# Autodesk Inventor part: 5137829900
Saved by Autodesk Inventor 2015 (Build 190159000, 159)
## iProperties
Created: 2020-07
Part Number: 5137829900
Checked By: TraceParts S.A.
Material: Generic
Catalog Web Link: www.traceparts.com
Document SubType Name: Modeling
Designer: TraceParts
Density: 1 g/cm^3
Appearance: Default
Company: TraceParts S.A.
Author: TraceParts
REFERENCE: 5137829900
DESIGN: CVAB-4000/400 N ECOWATT 0,45KW (230V 50/60HZ) N8 - 5137829900
SUPPLIER: Soler & Palau
TraceParts.PartNumber: 10-20122018-119636
TraceParts.PartTitle: CVAB/T-N_ECO
TraceParts.InstanceId: 10-20122018-1196363SL2A2IWXGLQZ48PNF08XPN57
TraceParts.PartStatus: Published
TraceParts.PartVersion: 1.0.2
TRACEPARTS: TRACEPARTS
TraceParts.PartLanguage: en
TraceParts.ClassPath: SOLER_PALAU:10-20122018-119636
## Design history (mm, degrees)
feature "5137829900"
body "Solid1"
